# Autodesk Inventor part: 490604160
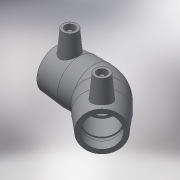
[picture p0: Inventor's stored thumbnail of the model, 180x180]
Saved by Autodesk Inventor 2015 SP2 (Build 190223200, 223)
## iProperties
Created: 2017-06
Part Number: 490604160
Material: Generic
Description: PLASSON 45° ELBOW 160
Document SubType Name: Modeling
Designer: KIM
Mass: 55.0731 g
Surface Area: 148.067 cm^2
Volume: 55.0731 cm^3
Density: 1 g/cm^3
Appearance: Default
Author: KIM
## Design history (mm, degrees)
derived "490604.ipt"
feature "Solid1::490604.ipt"
tag "TaggingFeature1"
body "Solid1"
other parameters: "d2" = 209, "d4" = 87.5, "d5" = 188.1, "d8" = 168 deg, "d10" = 38, "d11" = 12.66667, "d14" = 17.6296, "d19" = 3.52592, "d20" = 168 deg, "d22" = 192.28, "d23" = 209, "d24" = 186.5116, "d29" = 105, "d30" = 15, "d31" = 122.5, "d34" = 5 deg, "d35" = 12, "d39" = 0, "d41" = 4, "d42" = 14, "d43" = 0, "d44" = 9.6, "d45" = 4.8, "d46" = 6, "d47" = 0, "d50" = 136, "d51" = 38, "d52" = 95, "d54" = 135 deg, "d67" = 45 deg, "d71" = 135 deg, "d75" = 10.45, "d82" = 45 deg, "d83" = 95, "d84" = 188.1, "d86" = 94.05, "d87" = 135 deg, "d90" = 95, "d91" = 0, "d92" = 95, "d93" = 0, "d94" = 135 deg, "d95" = 96.14, "d99" = 105, "d101" = 3, "d102" = 0, "d103" = 3, "d104" = 0, "d105" = 27.55, "d106" = 6.8875, "L_1" = 95, "D_" = 209, "A_" = 105, "d_2" = 12
